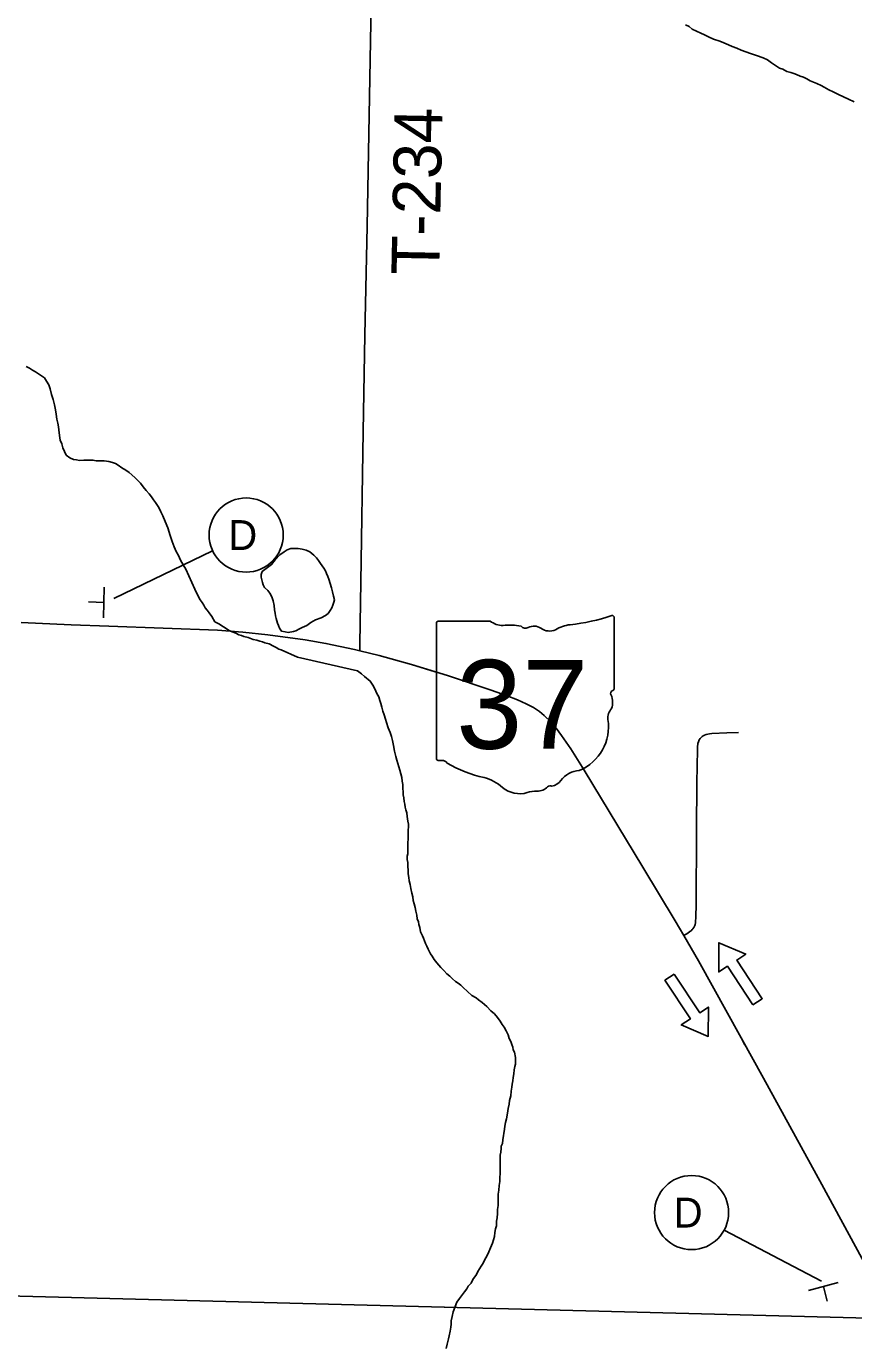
# Model space of a CAD drawing. Extents: x 1 to 1971, y -2 to 1107.
# Drawn here: x 1664.12 to 1668.44, y 1091.98 to 1098.86 of the extents above; entities that cross this region are included whole.
import ezdxf

# ---------------------------------------------------------------- set-up
doc = ezdxf.new("R2010")
doc.units = 0
for name, color, linetype in [('GM_X_Minor_Lake', 7, 'Continuous'), ('GM_X_Minor_River', 7, 'Continuous'), ('GM_X_State_Route', 7, 'Continuous'), ('GM_X_State_Shield', 7, 'Continuous'), ('GM_X_Township', 7, 'Continuous'), ('GM_X_Township_Road', 7, 'Continuous'), ('GM_X_Township_Road_Text', 7, 'Continuous'), ('SH_Text', 7, 'Continuous'), ('SN_P_Signs', 7, 'Continuous')]:
    doc.layers.add(name, color=color, linetype=linetype)

msp = doc.modelspace()

# ---------------------------------------------------------------- linework, layer by layer
at = {"layer": 'GM_X_Minor_Lake'}
for points in [[(1665.3546, 1096.0157), (1665.4034, 1096.0525), (1665.4225, 1096.0764), (1665.447, 1096.1029), (1665.4687, 1096.1186), (1665.4849, 1096.1291), (1665.5038, 1096.1369), (1665.5226, 1096.1367), (1665.5414, 1096.1364), (1665.5628, 1096.1335), (1665.5843, 1096.1279), (1665.6029, 1096.1196), (1665.6242, 1096.1005), (1665.6374, 1096.087), (1665.648, 1096.0734), (1665.6586, 1096.0572), (1665.677, 1096.0329), (1665.6849, 1096.0194), (1665.6901, 1096.0059), (1665.698, 1095.9897), (1665.7032, 1095.9763), (1665.716, 1095.9306), (1665.7211, 1095.9091), (1665.7263, 1095.8876), (1665.7314, 1095.8688), (1665.7285, 1095.8554), (1665.723, 1095.8394), (1665.7174, 1095.8261), (1665.7092, 1095.8128), (1665.6983, 1095.7969), (1665.6847, 1095.7863), (1665.663, 1095.7732), (1665.6334, 1095.7629), (1665.609, 1095.7498), (1665.5873, 1095.734), (1665.563, 1095.7236), (1665.5495, 1095.7158), (1665.5306, 1095.7053), (1665.5171, 1095.7028), (1665.4902, 1095.6978), (1665.4741, 1095.7007), (1665.4554, 1095.7036), (1665.4448, 1095.7198), (1665.4396, 1095.7333), (1665.4344, 1095.7468), (1665.4267, 1095.771), (1665.4242, 1095.7844), (1665.4217, 1095.7978), (1665.4192, 1095.8166), (1665.4168, 1095.8381), (1665.4117, 1095.8622), (1665.4039, 1095.8838), (1665.3934, 1095.9027), (1665.3829, 1095.9162), (1665.3669, 1095.9325), (1665.3591, 1095.946), (1665.3565, 1095.9594), (1665.3488, 1095.9863), (1665.349, 1095.9997), (1665.3546, 1096.0157)], [(1665.3546, 1096.0157), (1665.4034, 1096.0525), (1665.4225, 1096.0764), (1665.447, 1096.1029), (1665.4687, 1096.1186), (1665.4849, 1096.1291), (1665.5038, 1096.1369), (1665.5226, 1096.1367), (1665.5414, 1096.1364), (1665.5628, 1096.1335), (1665.5843, 1096.1279), (1665.6029, 1096.1196), (1665.6242, 1096.1005), (1665.6374, 1096.087), (1665.648, 1096.0734), (1665.6586, 1096.0572), (1665.677, 1096.0329), (1665.6849, 1096.0194), (1665.6901, 1096.0059), (1665.698, 1095.9897), (1665.7032, 1095.9763), (1665.716, 1095.9306), (1665.7211, 1095.9091), (1665.7263, 1095.8876), (1665.7314, 1095.8688), (1665.7285, 1095.8554), (1665.723, 1095.8394), (1665.7174, 1095.8261), (1665.7092, 1095.8128), (1665.6983, 1095.7969), (1665.6847, 1095.7863), (1665.663, 1095.7732), (1665.6334, 1095.7629), (1665.609, 1095.7498), (1665.5873, 1095.734), (1665.563, 1095.7236), (1665.5495, 1095.7158), (1665.5306, 1095.7053), (1665.5171, 1095.7028), (1665.4902, 1095.6978), (1665.4741, 1095.7007), (1665.4554, 1095.7036), (1665.4448, 1095.7198), (1665.4396, 1095.7333), (1665.4344, 1095.7468), (1665.4267, 1095.771), (1665.4242, 1095.7844), (1665.4217, 1095.7978), (1665.4192, 1095.8166), (1665.4168, 1095.8381), (1665.4117, 1095.8622), (1665.4039, 1095.8838), (1665.3934, 1095.9027), (1665.3829, 1095.9162), (1665.3669, 1095.9325), (1665.3591, 1095.946), (1665.3565, 1095.9594), (1665.3488, 1095.9863), (1665.349, 1095.9997), (1665.3546, 1096.0157)], [(1665.6983, 1095.7969), (1665.7092, 1095.8128), (1665.7174, 1095.8261), (1665.723, 1095.8394), (1665.7285, 1095.8554), (1665.7314, 1095.8688), (1665.7263, 1095.8876), (1665.7211, 1095.9091), (1665.716, 1095.9306), (1665.7032, 1095.9763), (1665.698, 1095.9897), (1665.6901, 1096.0059), (1665.6849, 1096.0194), (1665.677, 1096.0329), (1665.6586, 1096.0572), (1665.648, 1096.0734), (1665.6374, 1096.087), (1665.6242, 1096.1005), (1665.6029, 1096.1196), (1665.5843, 1096.1279), (1665.5628, 1096.1335), (1665.5414, 1096.1364), (1665.5226, 1096.1367), (1665.5038, 1096.1369), (1665.4849, 1096.1291), (1665.4687, 1096.1186), (1665.447, 1096.1029), (1665.4225, 1096.0764), (1665.4034, 1096.0525), (1665.3546, 1096.0157)], [(1665.6983, 1095.7969), (1665.7092, 1095.8128), (1665.7174, 1095.8261), (1665.723, 1095.8394), (1665.7285, 1095.8554), (1665.7314, 1095.8688), (1665.7263, 1095.8876), (1665.7211, 1095.9091), (1665.716, 1095.9306), (1665.7032, 1095.9763), (1665.698, 1095.9897), (1665.6901, 1096.0059), (1665.6849, 1096.0194), (1665.677, 1096.0329), (1665.6586, 1096.0572), (1665.648, 1096.0734), (1665.6374, 1096.087), (1665.6242, 1096.1005), (1665.6029, 1096.1196), (1665.5843, 1096.1279), (1665.5628, 1096.1335), (1665.5414, 1096.1364), (1665.5226, 1096.1367), (1665.5038, 1096.1369), (1665.4849, 1096.1291), (1665.4687, 1096.1186), (1665.447, 1096.1029), (1665.4225, 1096.0764), (1665.4034, 1096.0525), (1665.3546, 1096.0157)], [(1665.3546, 1096.0157), (1665.349, 1095.9997), (1665.3488, 1095.9863), (1665.3565, 1095.9594), (1665.3591, 1095.946), (1665.3669, 1095.9325), (1665.3829, 1095.9162), (1665.3934, 1095.9027), (1665.4039, 1095.8838), (1665.4117, 1095.8622), (1665.4168, 1095.8381), (1665.4192, 1095.8166), (1665.4217, 1095.7978), (1665.4242, 1095.7844), (1665.4267, 1095.771), (1665.4344, 1095.7468), (1665.4396, 1095.7333), (1665.4448, 1095.7198), (1665.4554, 1095.7036), (1665.4741, 1095.7007), (1665.4902, 1095.6978), (1665.5171, 1095.7028), (1665.5306, 1095.7053), (1665.5495, 1095.7158), (1665.563, 1095.7236), (1665.5873, 1095.734), (1665.609, 1095.7498), (1665.6334, 1095.7629), (1665.663, 1095.7732), (1665.6847, 1095.7863), (1665.6983, 1095.7969)], [(1665.3546, 1096.0157), (1665.349, 1095.9997), (1665.3488, 1095.9863), (1665.3565, 1095.9594), (1665.3591, 1095.946), (1665.3669, 1095.9325), (1665.3829, 1095.9162), (1665.3934, 1095.9027), (1665.4039, 1095.8838), (1665.4117, 1095.8622), (1665.4168, 1095.8381), (1665.4192, 1095.8166), (1665.4217, 1095.7978), (1665.4242, 1095.7844), (1665.4267, 1095.771), (1665.4344, 1095.7468), (1665.4396, 1095.7333), (1665.4448, 1095.7198), (1665.4554, 1095.7036), (1665.4741, 1095.7007), (1665.4902, 1095.6978), (1665.5171, 1095.7028), (1665.5306, 1095.7053), (1665.5495, 1095.7158), (1665.563, 1095.7236), (1665.5873, 1095.734), (1665.609, 1095.7498), (1665.6334, 1095.7629), (1665.663, 1095.7732), (1665.6847, 1095.7863), (1665.6983, 1095.7969)]]:
    msp.add_lwpolyline(points, dxfattribs=at)
at = {"layer": 'GM_X_Minor_River'}
for points in [[(1667.5659, 1098.8716), (1667.5846, 1098.8633), (1667.6005, 1098.8497), (1667.6459, 1098.8277), (1667.6646, 1098.8194), (1667.6859, 1098.8084), (1667.7127, 1098.7973), (1667.7447, 1098.7862), (1667.7661, 1098.7779), (1667.7901, 1098.7669), (1667.8088, 1098.7586), (1667.8329, 1098.7502), (1667.8569, 1098.7392), (1667.881, 1098.7309), (1667.9051, 1098.7225), (1667.9371, 1098.7114), (1667.9719, 1098.7002), (1667.9933, 1098.6892), (1668.0145, 1098.6728), (1668.0412, 1098.6564), (1668.0572, 1098.6455), (1668.0732, 1098.6399), (1668.0946, 1098.6289), (1668.116, 1098.6233), (1668.132, 1098.6177), (1668.1454, 1098.6122), (1668.1641, 1098.6039), (1668.1828, 1098.5983), (1668.1988, 1098.5901), (1668.2175, 1098.5791), (1668.2522, 1098.5653), (1668.2736, 1098.5543), (1668.2896, 1098.546), (1668.3136, 1098.5323), (1668.3376, 1098.5213)], [(1668.3376, 1098.5213), (1668.3643, 1098.5075), (1668.391, 1098.4965), (1668.4177, 1098.4827), (1668.4471, 1098.4689)], [(1664.122, 1097.0872), (1664.138, 1097.079), (1664.154, 1097.0681), (1664.17, 1097.0598), (1664.1859, 1097.0489), (1664.2019, 1097.038), (1664.2179, 1097.027), (1664.2284, 1097.0108), (1664.2389, 1096.9919), (1664.2467, 1096.9704), (1664.2544, 1096.9408), (1664.2621, 1096.914), (1664.2698, 1096.8871), (1664.2749, 1096.8602), (1664.2773, 1096.8388), (1664.2823, 1096.8119), (1664.2874, 1096.7904), (1664.2899, 1096.7716), (1664.2923, 1096.7555), (1664.2947, 1096.726)], [(1664.2947, 1096.726), (1664.2997, 1096.7019), (1664.3075, 1096.683), (1664.3127, 1096.6615), (1664.331, 1096.6238), (1664.3496, 1096.6101), (1664.3683, 1096.6018), (1664.3844, 1096.5989), (1664.4005, 1096.5961), (1664.422, 1096.5985), (1664.4381, 1096.5982), (1664.4542, 1096.598), (1664.4703, 1096.5978), (1664.4864, 1096.5949), (1664.4998, 1096.5948), (1664.5159, 1096.5945), (1664.5293, 1096.5944), (1664.5535, 1096.5914), (1664.5722, 1096.5858), (1664.5882, 1096.5802), (1664.6016, 1096.572), (1664.6202, 1096.5584), (1664.6415, 1096.5447), (1664.6602, 1096.5337), (1664.6894, 1096.5066), (1664.7026, 1096.493), (1664.7185, 1096.4767), (1664.7317, 1096.4578), (1664.7476, 1096.4388), (1664.7635, 1096.4225), (1664.7767, 1096.4063), (1664.7873, 1096.3901), (1664.7978, 1096.3766), (1664.8136, 1096.3496), (1664.8241, 1096.328), (1664.8345, 1096.3064), (1664.8476, 1096.2768), (1664.8606, 1096.2445), (1664.8735, 1096.2041), (1664.8839, 1096.1719), (1664.8943, 1096.1449), (1664.9047, 1096.1207), (1664.9179, 1096.0991), (1664.9283, 1096.0748), (1664.9414, 1096.0506), (1664.9546, 1096.029), (1665.0016, 1095.9239), (1665.0173, 1095.8915), (1665.0304, 1095.8672), (1665.041, 1095.8537), (1665.0489, 1095.8402), (1665.0568, 1095.8267), (1665.0674, 1095.8132), (1665.0779, 1095.7997), (1665.0911, 1095.7807), (1665.1069, 1095.7537), (1665.1282, 1095.7427), (1665.1522, 1095.7263), (1665.1655, 1095.7181), (1665.1788, 1095.7099), (1665.1975, 1095.7017), (1665.2162, 1095.6934), (1665.2322, 1095.6851), (1665.2456, 1095.6823), (1665.259, 1095.6767), (1665.2804, 1095.6711), (1665.3071, 1095.66), (1665.3259, 1095.6571), (1665.3419, 1095.6515), (1665.3553, 1095.6487), (1665.3687, 1095.6432), (1665.3901, 1095.6375), (1665.4141, 1095.6265), (1665.4275, 1095.6183), (1665.4408, 1095.6101), (1665.4542, 1095.6072), (1665.5385, 1095.568)], [(1665.5385, 1095.568), (1665.852, 1095.4974), (1665.8733, 1095.4813), (1665.8894, 1095.4679), (1665.9187, 1095.4437), (1665.9321, 1095.4222), (1665.9427, 1095.4035), (1665.9534, 1095.3794), (1665.964, 1095.3606), (1665.9693, 1095.3419), (1665.9747, 1095.3258), (1665.98, 1095.307), (1665.9853, 1095.2856), (1665.9906, 1095.2669), (1665.9986, 1095.2454), (1666.0039, 1095.2267), (1666.0118, 1095.1999), (1666.0225, 1095.1758), (1666.0305, 1095.1544), (1666.0358, 1095.1329), (1666.041, 1095.1062), (1666.0463, 1095.0767), (1666.0516, 1095.05), (1666.0569, 1095.0312), (1666.0622, 1095.0125), (1666.0676, 1094.9964), (1666.0729, 1094.9777), (1666.0782, 1094.9589), (1666.0835, 1094.9402), (1666.0861, 1094.9214), (1666.0887, 1094.9027), (1666.0887, 1094.884), (1666.0913, 1094.8625), (1666.0913, 1094.8492), (1666.0939, 1094.8331), (1666.0966, 1094.8144), (1666.0992, 1094.801), (1666.1019, 1094.7849), (1666.1045, 1094.7715), (1666.1098, 1094.7555), (1666.1124, 1094.7367), (1666.1151, 1094.7126), (1666.1177, 1094.6966), (1666.1176, 1094.6511), (1666.1176, 1094.6377), (1666.1175, 1094.6217), (1666.1148, 1094.5976), (1666.1148, 1094.5789), (1666.1147, 1094.5548), (1666.1147, 1094.5414), (1666.112, 1094.5281), (1666.1119, 1094.512), (1666.1146, 1094.4959), (1666.1145, 1094.4745), (1666.1172, 1094.4558), (1666.1171, 1094.4371), (1666.1197, 1094.4183), (1666.1224, 1094.3996), (1666.1277, 1094.3808), (1666.1303, 1094.3594), (1666.1356, 1094.3353), (1666.1409, 1094.3166), (1666.1435, 1094.2979), (1666.1489, 1094.2791), (1666.1542, 1094.2604), (1666.1568, 1094.2416), (1666.1621, 1094.2202), (1666.1647, 1094.2015), (1666.17, 1094.1854), (1666.1727, 1094.172), (1666.178, 1094.1559), (1666.1806, 1094.1345), (1666.1913, 1094.1131), (1666.1966, 1094.0997), (1666.2019, 1094.0863), (1666.2072, 1094.0729), (1666.2152, 1094.0595), (1666.2205, 1094.0434), (1666.2339, 1094.0193), (1666.2419, 1094.0059), (1666.2525, 1093.9898), (1666.2659, 1093.971), (1666.2872, 1093.9469), (1666.3033, 1093.9308), (1666.3193, 1093.9147), (1666.3353, 1093.9013), (1666.3486, 1093.8878), (1666.3647, 1093.8744), (1666.378, 1093.8663), (1666.3914, 1093.8556), (1666.4047, 1093.8422), (1666.4501, 1093.8019), (1666.4715, 1093.7885), (1666.4848, 1093.7777), (1666.5035, 1093.7643), (1666.5276, 1093.7428), (1666.5489, 1093.7213), (1666.5676, 1093.7052), (1666.5836, 1093.6864), (1666.597, 1093.6677), (1666.6076, 1093.6489)], [(1666.6076, 1093.6489), (1666.6183, 1093.6355), (1666.629, 1093.6167), (1666.6396, 1093.5953), (1666.6449, 1093.5765), (1666.6529, 1093.5605), (1666.6582, 1093.5444), (1666.6636, 1093.531), (1666.6662, 1093.5176), (1666.6715, 1093.5042), (1666.6768, 1093.4775), (1666.6768, 1093.4614), (1666.6767, 1093.4427), (1666.674, 1093.4293), (1666.6713, 1093.4132), (1666.6686, 1093.3919), (1666.6659, 1093.3731), (1666.6631, 1093.3544), (1666.6604, 1093.3384), (1666.6577, 1093.3223), (1666.655, 1093.3009), (1666.6523, 1093.2769), (1666.6469, 1093.2528), (1666.6441, 1093.2341), (1666.6387, 1093.21), (1666.636, 1093.1859), (1666.6306, 1093.1565), (1666.6252, 1093.1378), (1666.6225, 1093.1191), (1666.6198, 1093.1031), (1666.6116, 1093.0469), (1666.6089, 1093.0282), (1666.6035, 1093.0148), (1666.6035, 1093.0014), (1666.6007, 1092.9827), (1666.598, 1092.9667), (1666.598, 1092.9373), (1666.5979, 1092.9158), (1666.5979, 1092.8918), (1666.5978, 1092.873), (1666.5951, 1092.849), (1666.595, 1092.8302), (1666.5923, 1092.8089), (1666.5896, 1092.7848), (1666.5869, 1092.7634), (1666.5868, 1092.7286), (1666.5867, 1092.7045), (1666.584, 1092.6831), (1666.584, 1092.6617), (1666.5812, 1092.6403), (1666.5785, 1092.6216), (1666.5785, 1092.5975), (1666.5731, 1092.5815), (1666.5703, 1092.5628), (1666.5676, 1092.5414), (1666.5622, 1092.5253), (1666.5568, 1092.5066), (1666.5461, 1092.4826), (1666.538, 1092.4612), (1666.5273, 1092.4398), (1666.5165, 1092.4211), (1666.5084, 1092.4024), (1666.4977, 1092.3864), (1666.4896, 1092.3731), (1666.4816, 1092.3597), (1666.4735, 1092.3437), (1666.4547, 1092.317), (1666.4467, 1092.2983), (1666.4306, 1092.2823), (1666.4225, 1092.2689), (1666.4118, 1092.2529), (1666.401, 1092.2396), (1666.3849, 1092.2182), (1666.3715, 1092.1995), (1666.3527, 1092.1488), (1666.3473, 1092.1247), (1666.3419, 1092.1007), (1666.3418, 1092.0846), (1666.3391, 1092.0685), (1666.3364, 1092.0472), (1666.331, 1092.0231), (1666.3283, 1092.007), (1666.3202, 1091.9803), (1666.3148, 1091.9563)]]:
    msp.add_lwpolyline(points, dxfattribs=at)
at = {"layer": 'GM_X_State_Route'}
for points in [[(1664.0954, 1095.7491), (1664.3558, 1095.737), (1664.5527, 1095.7309), (1665.1216, 1095.7091), (1665.2528, 1095.6999), (1665.3836, 1095.6854), (1665.5789, 1095.6584), (1665.6871, 1095.6403), (1665.8373, 1095.6085), (1665.8647, 1095.6018)], [(1665.8647, 1095.6018), (1665.965, 1095.5772), (1666.134, 1095.5304), (1666.3224, 1095.4721), (1666.5511, 1095.3957), (1666.6338, 1095.3657), (1666.6887, 1095.3448), (1666.7333, 1095.3248), (1666.7723, 1095.3047), (1666.8024, 1095.2846), (1666.8281, 1095.2635), (1666.8616, 1095.2312), (1666.8894, 1095.1977), (1666.9173, 1095.1598), (1666.966, 1095.0892), (1667.036, 1094.9775), (1667.3422, 1094.472), (1667.5124, 1094.191), (1667.5577, 1094.1145), (1667.6338, 1093.9829), (1667.8558, 1093.5802), (1667.8763, 1093.5432)]]:
    msp.add_lwpolyline(points, dxfattribs=at)
at = {"layer": 'GM_X_State_Shield'}
for p, q in [((1666.2648, 1095.7448), (1666.2648, 1095.0404)), ((1666.5457, 1095.7569), (1666.2739, 1095.7569)), ((1667.1929, 1095.4059), (1667.1929, 1095.7744)), ((1667.1928, 1095.406), (1667.1929, 1095.4059))]:
    msp.add_line(p, q, dxfattribs=at)
for centre, radius, start, end in [((1666.2754, 1095.7463), 0.0108, 98.1301, 188.1301), ((1666.6104, 1095.8387), 0.1043, 231.61951, 271.11188), ((1666.8623, 1096.7173), 0.9842, 275.84447, 288.90645), ((1667.1826, 1095.7759), 0.0103, 351.86209, 97.738), ((1666.645, 1095.3615), 0.3744, 80.48669, 94.98827), ((1666.73, 1095.75), 0.0301, 219.79206, 297.10237), ((1666.7742, 1095.6685), 0.0626, 54.46668, 119.14113), ((1666.8549, 1095.7802), 0.0753, 233.85621, 294.82819), ((1666.9878, 1095.5418), 0.198, 97.34618, 120.76885), ((1667.1819, 1095.4045), 0.0111, 289.60381, 7.73413), ((1667.1905, 1095.3788), 0.016, 107.94398, 210.33697), ((1667.0888, 1095.3323), 0.096, 340.03296, 23.64957), ((1667.2299, 1095.2517), 0.0698, 136.8065, 186.92959), ((1666.9174, 1095.2048), 0.2462, 292.30889, 8.98584), ((1666.2755, 1095.0388), 0.0108, 171.95839, 258.30661), ((1666.2771, 1095.1109), 0.0828, 267.33899, 280.60386), ((1666.2941, 1094.9997), 0.0298, 29.74838, 93.27175), ((1666.6709, 1095.6326), 0.7108, 240.41292, 257.1985), ((1666.459, 1094.7239), 0.2224, 47.18416, 75.83597), ((1666.8504, 1094.9721), 0.0795, 282.87319, 323.27711), ((1667.0212, 1094.8426), 0.1348, 94.40312, 142.57675), ((1666.6995, 1094.9963), 0.1411, 230.70037, 286.29184), ((1666.7811, 1094.7527), 0.116, 85.69512, 111.20995), ((1666.7914, 1094.9435), 0.0752, 268.77702, 315.54927), ((1666.8594, 1094.8753), 0.0212, 65.75173, 132.64842)]:
    msp.add_arc(centre, radius, start, end, dxfattribs=at)
at = {"layer": 'GM_X_Township'}
msp.add_lwpolyline([(1653.1763, 1092.4976), (1656.8592, 1092.4086), (1656.9549, 1092.4071), (1660.4424, 1092.2976), (1663.9517, 1092.2334), (1668.658, 1092.1116), (1671.0761, 1092.0354), (1672.2022, 1091.993)], dxfattribs=at)
at = {"layer": 'GM_X_Township_Road'}
for points in [[(1665.8647, 1095.6018), (1665.8652, 1095.6384), (1665.8691, 1095.9598), (1665.8824, 1096.7478), (1665.891, 1097.2512), (1665.9023, 1097.8203), (1665.9237, 1098.9803), (1665.9265, 1099.243), (1665.9316, 1099.5056), (1665.9414, 1100.206), (1665.9454, 1100.3592), (1665.9448, 1100.4293)], [(1665.8647, 1095.6018), (1665.8652, 1095.6384), (1665.8691, 1095.9598), (1665.8824, 1096.7478), (1665.891, 1097.2512), (1665.9023, 1097.8203), (1665.9237, 1098.9803), (1665.9265, 1099.243), (1665.9316, 1099.5056), (1665.9414, 1100.206), (1665.9454, 1100.3592), (1665.9448, 1100.4293)], [(1667.5577, 1094.1145), (1667.5775, 1094.1268), (1667.589, 1094.1347), (1667.5944, 1094.1394), (1667.6009, 1094.1459), (1667.6038, 1094.1495), (1667.6084, 1094.1559), (1667.6111, 1094.1605), (1667.6138, 1094.167), (1667.6156, 1094.1728), (1667.6172, 1094.1807), (1667.6185, 1094.1914), (1667.6193, 1094.2042), (1667.6193, 1094.2194), (1667.6207, 1094.2688), (1667.6207, 1094.2939), (1667.6212, 1094.3872), (1667.6229, 1094.544), (1667.6231, 1094.6665), (1667.6252, 1094.9115), (1667.6279, 1095.0865), (1667.6285, 1095.0992), (1667.6288, 1095.1039), (1667.6296, 1095.1121), (1667.6306, 1095.1176), (1667.6328, 1095.1261), (1667.6347, 1095.1314), (1667.6375, 1095.137), (1667.6425, 1095.1441), (1667.6481, 1095.1497), (1667.6527, 1095.1538), (1667.6583, 1095.1575), (1667.6649, 1095.1609), (1667.673, 1095.1638), (1667.6814, 1095.166), (1667.6914, 1095.1681), (1667.703, 1095.1692), (1667.7818, 1095.173), (1667.8432, 1095.1752)], [(1667.5577, 1094.1145), (1667.5775, 1094.1268), (1667.589, 1094.1347), (1667.5944, 1094.1394), (1667.6009, 1094.1459), (1667.6038, 1094.1495), (1667.6084, 1094.1559), (1667.6111, 1094.1605), (1667.6138, 1094.167), (1667.6156, 1094.1728), (1667.6172, 1094.1807), (1667.6185, 1094.1914), (1667.6193, 1094.2042), (1667.6193, 1094.2194), (1667.6207, 1094.2688), (1667.6207, 1094.2939), (1667.6212, 1094.3872), (1667.6229, 1094.544), (1667.6231, 1094.6665), (1667.6252, 1094.9115), (1667.6279, 1095.0865), (1667.6285, 1095.0992), (1667.6288, 1095.1039), (1667.6296, 1095.1121), (1667.6306, 1095.1176), (1667.6328, 1095.1261), (1667.6347, 1095.1314), (1667.6375, 1095.137), (1667.6425, 1095.1441), (1667.6481, 1095.1497), (1667.6527, 1095.1538), (1667.6583, 1095.1575), (1667.6649, 1095.1609), (1667.673, 1095.1638), (1667.6814, 1095.166), (1667.6914, 1095.1681), (1667.703, 1095.1692), (1667.7818, 1095.173), (1667.8432, 1095.1752)]]:
    msp.add_lwpolyline(points, dxfattribs=at)
at = {"layer": 'SH_Text'}
for p, q in [((1664.5796, 1095.8749), (1665.0953, 1096.1242)), ((1667.7395, 1094.0769), (1667.7389, 1093.9238)), ((1667.7395, 1094.0769), (1667.8805, 1094.0171)), ((1667.7389, 1093.9238), (1667.7845, 1093.9538)), ((1667.7845, 1093.9538), (1667.9178, 1093.7518)), ((1667.8805, 1094.0171), (1667.8329, 1093.9857)), ((1667.8329, 1093.9857), (1667.9662, 1093.7837)), ((1667.4579, 1093.8809), (1667.5064, 1093.9128)), ((1667.6396, 1093.7108), (1667.5064, 1093.9128)), ((1667.5912, 1093.6788), (1667.4579, 1093.8809)), ((1667.9662, 1093.7837), (1667.9178, 1093.7518)), ((1667.5436, 1093.6474), (1667.5912, 1093.6788)), ((1667.6852, 1093.7408), (1667.6396, 1093.7108)), ((1667.6846, 1093.5877), (1667.6852, 1093.7408)), ((1667.6846, 1093.5877), (1667.5436, 1093.6474)), ((1668.2753, 1092.3093), (1667.7679, 1092.5751))]:
    msp.add_line(p, q, dxfattribs=at)
for points in [[(1664.0954, 1095.7491), (1664.3558, 1095.737), (1664.5527, 1095.7309), (1665.1216, 1095.7091), (1665.2528, 1095.6999), (1665.3836, 1095.6854), (1665.5789, 1095.6584), (1665.6871, 1095.6403), (1665.8373, 1095.6085), (1665.8647, 1095.6018)], [(1665.8647, 1095.6018), (1665.965, 1095.5772), (1666.134, 1095.5304), (1666.2582, 1095.492)], [(1667.0331, 1094.9821), (1667.036, 1094.9775), (1667.3422, 1094.472), (1667.5124, 1094.191), (1667.5577, 1094.1145), (1667.6338, 1093.9829), (1667.8558, 1093.5802), (1667.9723, 1093.3696), (1668.2781, 1092.8131), (1668.4867, 1092.4282), (1668.6651, 1092.0989), (1668.7474, 1091.947), (1669.0282, 1091.4269), (1669.2085, 1091.0948), (1669.731, 1090.1531)]]:
    msp.add_lwpolyline(points, dxfattribs=at)
for points in [[(1667.9177, 1093.7518), (1667.7845, 1093.9538), (1667.7389, 1093.9238), (1667.7395, 1094.0769), (1667.8805, 1094.0171), (1667.8329, 1093.9857), (1667.9662, 1093.7837)], [(1667.5064, 1093.9128), (1667.6396, 1093.7108), (1667.6852, 1093.7408), (1667.6846, 1093.5877), (1667.5436, 1093.6474), (1667.5912, 1093.6788), (1667.458, 1093.8809)]]:
    msp.add_lwpolyline(points, close=True, dxfattribs=at)
for centre in [(1665.2706, 1096.2065), (1667.5974, 1092.667)]:
    msp.add_circle(centre, 0.1936, dxfattribs=at)
at = {"layer": 'SN_P_Signs'}
for p, q in [((1664.5247, 1095.7747), (1664.5295, 1095.9347)), ((1664.5271, 1095.8547), (1664.4471, 1095.8571)), ((1668.3631, 1092.3014), (1668.2085, 1092.2602)), ((1668.2858, 1092.2808), (1668.3064, 1092.2035))]:
    msp.add_line(p, q, dxfattribs=at)

# ---------------------------------------------------------------- texts
at = {"layer": 'GM_X_State_Shield'}
msp.add_text('37', height=0.46406, dxfattribs=at).set_placement((1666.3678, 1095.0901))
at = {"layer": 'GM_X_Township_Road_Text'}
msp.add_text('T-234', height=0.25, rotation=88.87238, dxfattribs=at).set_placement((1666.2787, 1097.5635))
at = {"layer": 'SH_Text'}
for p in [(1665.1776, 1096.1285), (1667.5044, 1092.589)]:
    msp.add_text('D', height=0.156, dxfattribs=at).set_placement(p)

doc.saveas('drawing.dxf')
